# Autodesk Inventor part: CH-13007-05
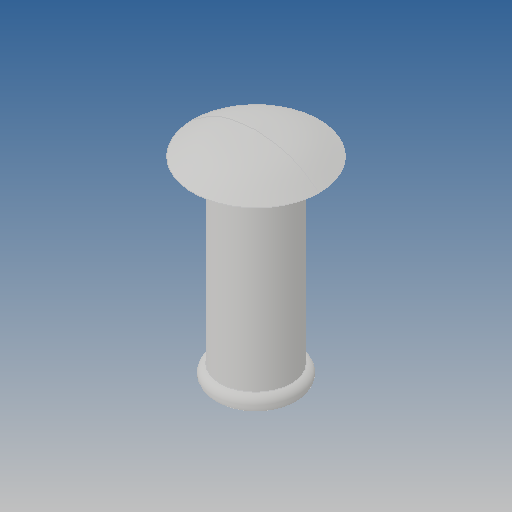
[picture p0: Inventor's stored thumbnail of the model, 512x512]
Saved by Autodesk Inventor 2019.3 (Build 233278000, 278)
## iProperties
Created: 2017-11
Part Number: CH-13007-05
Material: Ogólny
Document SubType Name: Modeling
Designer: Admin
Density: 1 g/cm^3
Appearance: Domyślna
Author: Admin
Revision Number: ÈÎºÎ
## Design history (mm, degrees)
feature "Ðý×ª1"
node "Bryła1"
